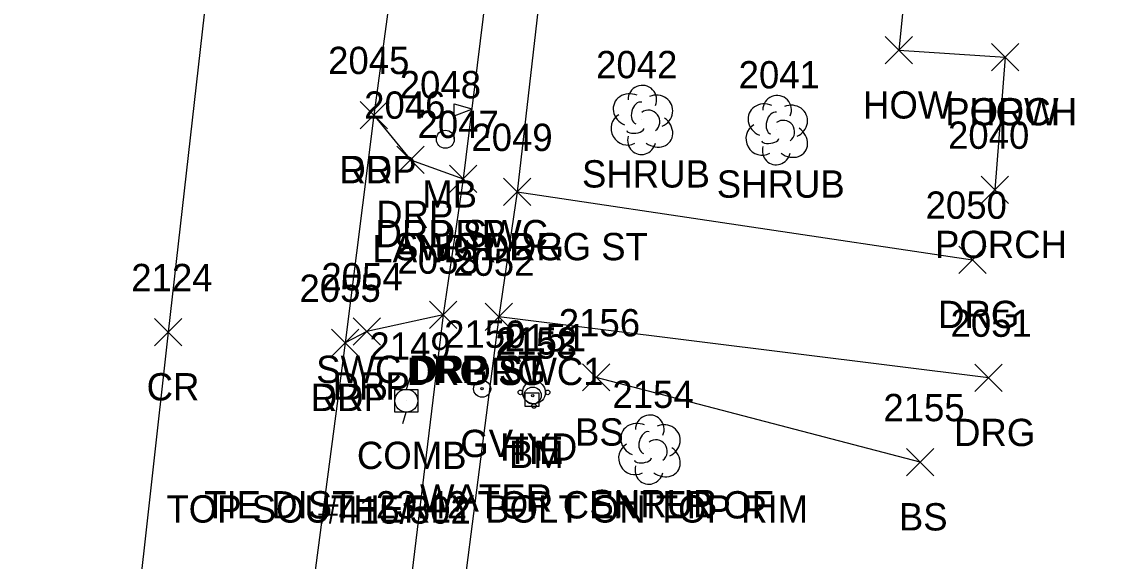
# Model space of a CAD drawing. Extents: x 1651305 to 1654558, y 539481 to 548441.
# Drawn here: x 1654363.2 to 1654443.3, y 544258.1 to 544297.6 of the extents above; entities that cross this region are included whole.
import ezdxf

# ---------------------------------------------------------------- set-up
doc = ezdxf.new("R2010")
doc.units = 0
for name, color, linetype in [('C_A', 7, 'Continuous'), ('C_C', 7, 'Continuous'), ('C_I', 7, 'Continuous'), ('CBP', 7, 'Continuous'), ('CPBM', 7, 'Continuous'), ('L_A', 7, 'Continuous'), ('L_C', 7, 'Continuous'), ('L_I', 7, 'Continuous'), ('L_TIC', 7, 'Continuous'), ('LBC', 7, 'Continuous'), ('LBF', 7, 'Continuous'), ('LELB', 7, 'Continuous'), ('LMB', 7, 'Continuous'), ('LSH', 7, 'Continuous'), ('P_A', 7, 'Continuous'), ('P_I', 7, 'Continuous'), ('P_TIC', 7, 'Continuous'), ('PET', 7, 'Continuous'), ('PRC', 7, 'Continuous'), ('R_A', 7, 'Continuous'), ('R_I', 7, 'Continuous'), ('R_TIC', 7, 'Continuous'), ('RDG', 7, 'Continuous'), ('RDP', 7, 'Continuous'), ('RSW', 7, 'Continuous'), ('U_A', 7, 'Continuous'), ('U_C', 7, 'Continuous'), ('U_I', 7, 'Continuous'), ('UP', 7, 'Continuous'), ('UWFH', 7, 'Continuous'), ('UWV', 7, 'Continuous')]:
    doc.layers.add(name, color=color, linetype=linetype)

msp = doc.modelspace()

# ---------------------------------------------------------------- linework, layer by layer
at = {"layer": 'CBP'}
for radius in [0.625, 0.0833]:
    msp.add_circle((1654400.576, 544270.202), radius, dxfattribs=at)
at = {"layer": 'CPBM'}
for p, q in [((1654400.022, 544269.4), (1654400.022, 544270.4)), ((1654400.022, 544270.4), (1654401.022, 544270.4)), ((1654400.525, 544269.9), (1654400.525, 544269.9)), ((1654400.525, 544269.9), (1654400.525, 544269.9)), ((1654401.022, 544270.4), (1654401.022, 544269.4)), ((1654401.022, 544269.4), (1654400.022, 544269.4))]:
    msp.add_line(p, q, dxfattribs=at)
at = {"layer": 'L_TIC'}
for points in [[(1654426.363, 544294.483), (1654428.363, 544296.483)], [(1654428.363, 544294.483), (1654426.363, 544296.483)], [(1654434.139, 544293.979), (1654436.139, 544295.979)], [(1654436.139, 544293.979), (1654434.139, 544295.979)], [(1654434.139, 544293.979), (1654436.139, 544295.979)], [(1654436.139, 544293.979), (1654434.139, 544295.979)], [(1654433.393, 544284.264), (1654435.393, 544286.264)], [(1654435.393, 544284.264), (1654433.393, 544286.264)], [(1654404.231, 544270.535), (1654406.231, 544272.535)], [(1654406.231, 544270.535), (1654404.231, 544272.535)], [(1654427.928, 544264.323), (1654429.928, 544266.323)], [(1654429.928, 544264.323), (1654427.928, 544266.323)]]:
    msp.add_lwpolyline(points, dxfattribs=at)
at = {"layer": 'LBC'}
msp.add_lwpolyline([(1654438.268, 544331.324), (1654431.161, 544332.043), (1654429.48, 544317.688), (1654428.83, 544310.138), (1654427.363, 544295.483), (1654435.139, 544294.979)], dxfattribs=at)
at = {"layer": 'LBF'}
msp.add_lwpolyline([(1654435.139, 544294.979), (1654434.393, 544285.264)], dxfattribs=at)
at = {"layer": 'LELB'}
msp.add_lwpolyline([(1654428.928, 544265.323), (1654405.231, 544271.535)], dxfattribs=at)
at = {"layer": 'LMB'}
for p, q in [((1654394.831, 544291.567), (1654396.125, 544291.185)), ((1654394.837, 544288.975), (1654394.836, 544291.57)), ((1654394.836, 544290.668), (1654396.118, 544291.176)), ((1654394.181, 544288.967), (1654394.181, 544288.967))]:
    msp.add_line(p, q, dxfattribs=at)
msp.add_circle((1654394.181, 544288.966), 0.656, dxfattribs=at)
at = {"layer": 'LSH'}
for p, q in [((1654408.551, 544290.431), (1654408.551, 544290.431)), ((1654408.551, 544290.431), (1654408.551, 544290.431)), ((1654418.416, 544289.685), (1654418.416, 544289.685)), ((1654418.416, 544289.685), (1654418.416, 544289.685)), ((1654409.099, 544266.297), (1654409.099, 544266.297)), ((1654409.099, 544266.297), (1654409.099, 544266.297))]:
    msp.add_line(p, q, dxfattribs=at)
for centre in [(1654408.598, 544291.865), (1654418.463, 544291.119), (1654409.146, 544267.731)]:
    msp.add_arc(centre, 1.047, 335.52715, 180.95627, dxfattribs=at)
for centre, major_axis, ratio, start_param, end_param in [((1654407.759, 544291.097), (1.21, -0.512), 0.895232, 1.570796, 4.712389), ((1654409.592, 544291.014), (-1.141, -0.483), 0.949671, 1.570796, 4.712389), ((1654408.342, 544290.889), (-0.208, -0.792), 0.645439, 3.141593, 6.283185), ((1654417.624, 544290.352), (1.21, -0.512), 0.895232, 1.570796, 4.712389), ((1654419.458, 544290.269), (-1.141, -0.483), 0.949671, 1.570796, 4.712389), ((1654407.468, 544289.722), (0.584, -1.042), 0.959034, 3.141593, 6.283185), ((1654409.051, 544290.264), (-0.5, 0.667), 0.989748, 3.141593, 6.283185), ((1654409.551, 544289.598), (-1.09, 0.792), 0.841452, 1.570796, 4.712389), ((1654418.208, 544290.144), (-0.208, -0.792), 0.645439, 3.141593, 6.283185), ((1654408.093, 544289.681), (-0.625, -0.083), 0.423636, 0, 3.141593), ((1654417.333, 544288.977), (0.584, -1.042), 0.959034, 3.141593, 6.283185), ((1654418.916, 544289.519), (-0.5, 0.667), 0.989748, 3.141593, 6.283185), ((1654419.416, 544288.852), (-1.09, 0.792), 0.841452, 1.570796, 4.712389), ((1654408.551, 544288.931), (0.265, 1.061), 0.942809, 1.570796, 4.712389), ((1654417.958, 544288.935), (-0.625, -0.083), 0.423636, 0, 3.141593), ((1654418.416, 544288.185), (0.265, 1.061), 0.942809, 1.570796, 4.712389), ((1654408.307, 544266.963), (1.21, -0.512), 0.895232, 1.570796, 4.712389), ((1654410.141, 544266.88), (-1.141, -0.483), 0.949671, 1.570796, 4.712389), ((1654408.891, 544266.755), (-0.208, -0.792), 0.645439, 3.141593, 6.283185), ((1654408.016, 544265.588), (0.584, -1.042), 0.959034, 3.141593, 6.283185), ((1654409.599, 544266.13), (-0.5, 0.667), 0.989748, 3.141593, 6.283185), ((1654410.099, 544265.464), (-1.09, 0.792), 0.841452, 1.570796, 4.712389), ((1654409.099, 544264.797), (0.265, 1.061), 0.942809, 1.570796, 4.712389), ((1654408.641, 544265.547), (-0.625, -0.083), 0.423636, 0, 3.141593)]:
    msp.add_ellipse(centre, major_axis=major_axis, ratio=ratio, start_param=start_param, end_param=end_param, dxfattribs=at)
at = {"layer": 'P_TIC'}
for points in [[(1654387.941, 544289.736), (1654389.941, 544291.736)], [(1654389.941, 544289.736), (1654387.941, 544291.736)], [(1654372.889, 544273.842), (1654374.889, 544275.842)], [(1654374.889, 544273.842), (1654372.889, 544275.842)], [(1654385.845, 544273.06), (1654387.845, 544275.06)], [(1654387.845, 544273.06), (1654385.845, 544275.06)]]:
    msp.add_lwpolyline(points, dxfattribs=at)
at = {"layer": 'PET'}
msp.add_lwpolyline([(1654345.042, 544588.36), (1654350.59, 544607.191), (1654356.582, 544624.309), (1654366.692, 544597.705), (1654378.699, 544565.627), (1654388.798, 544536.019), (1654394.392, 544506.433), (1654399.121, 544481.008), (1654401.125, 544462.893), (1654401.531, 544436.346), (1654401.825, 544421.309), (1654397.366, 544359.696), (1654394.392, 544336.586), (1654391.404, 544308.963), (1654388.941, 544290.736), (1654386.845, 544274.06), (1654380.974, 544229.445), (1654377.749, 544202.908), (1654375.628, 544181.037), (1654372.192, 544149.754), (1654366.612, 544105.723), (1654362.798, 544072.788)], dxfattribs=at)
at = {"layer": 'PRC'}
msp.add_lwpolyline([(1654350.59, 544607.191), (1654355.931, 544592.699), (1654363.685, 544570.628), (1654372.223, 544542.272), (1654380.244, 544505.389), (1654384.95, 544473.916), (1654386.821, 544433.75), (1654385.713, 544395.522), (1654383.86, 544365.997), (1654380.919, 544339.646), (1654377.996, 544311.086), (1654373.889, 544274.842), (1654369.008, 544231.012), (1654366.63, 544212.463), (1654362.444, 544177.974), (1654359.488, 544151.886), (1654354.071, 544107.932), (1654348.42, 544063.008)], dxfattribs=at)
at = {"layer": 'R_TIC'}
for points in [[(1654387.941, 544289.736), (1654389.941, 544291.736)], [(1654389.941, 544289.736), (1654387.941, 544291.736)], [(1654390.633, 544286.466), (1654392.633, 544288.466)], [(1654392.633, 544286.466), (1654390.633, 544288.466)], [(1654394.487, 544285.058), (1654396.487, 544287.058)], [(1654396.487, 544285.058), (1654394.487, 544287.058)], [(1654394.487, 544285.058), (1654396.487, 544287.058)], [(1654396.487, 544285.058), (1654394.487, 544287.058)], [(1654398.432, 544284.106), (1654400.432, 544286.106)], [(1654400.432, 544284.106), (1654398.432, 544286.106)], [(1654398.432, 544284.106), (1654400.432, 544286.106)], [(1654400.432, 544284.106), (1654398.432, 544286.106)], [(1654431.752, 544279.142), (1654433.752, 544281.142)], [(1654433.752, 544279.142), (1654431.752, 544281.142)], [(1654393.013, 544275.122), (1654395.013, 544277.122)], [(1654395.013, 544275.122), (1654393.013, 544277.122)], [(1654393.013, 544275.122), (1654395.013, 544277.122)], [(1654395.013, 544275.122), (1654393.013, 544277.122)], [(1654397.089, 544274.966), (1654399.089, 544276.966)], [(1654399.089, 544274.966), (1654397.089, 544276.966)], [(1654397.089, 544274.966), (1654399.089, 544276.966)], [(1654399.089, 544274.966), (1654397.089, 544276.966)], [(1654387.448, 544273.9), (1654389.448, 544275.9)], [(1654389.448, 544273.9), (1654387.448, 544275.9)], [(1654385.845, 544273.06), (1654387.845, 544275.06)], [(1654387.845, 544273.06), (1654385.845, 544275.06)], [(1654432.922, 544270.501), (1654434.922, 544272.501)], [(1654434.922, 544270.501), (1654432.922, 544272.501)]]:
    msp.add_lwpolyline(points, dxfattribs=at)
at = {"layer": 'RDG'}
for points in [[(1654399.432, 544285.106), (1654432.752, 544280.142)], [(1654433.922, 544271.501), (1654398.089, 544275.966)]]:
    msp.add_lwpolyline(points, dxfattribs=at)
at = {"layer": 'RDP'}
for points in [[(1654388.941, 544290.736), (1654391.633, 544287.466), (1654395.487, 544286.058)], [(1654394.013, 544276.122), (1654388.448, 544274.9), (1654386.845, 544274.06)]]:
    msp.add_lwpolyline(points, dxfattribs=at)
at = {"layer": 'RSW'}
for points in [[(1654407.404, 544661.775), (1654407.293, 544658.868), (1654407.962, 544657.877), (1654443.269, 544654.592), (1654438.81, 544619.894), (1654433.558, 544580.17), (1654430.136, 544553.995), (1654428.025, 544537.281), (1654424.833, 544512.838), (1654419.77, 544473.615), (1654412.659, 544419.662), (1654404.122, 544354.774), (1654402.102, 544339.773), (1654395.487, 544286.058), (1654394.013, 544276.122), (1654388.386, 544229.583), (1654383.891, 544196.376), (1654382.201, 544184.333), (1654378.352, 544149.148), (1654372.361, 544105.495), (1654368.546, 544072.052)], [(1654433.769, 544447.317), (1654420.392, 544448.732), (1654416.298, 544419.47), (1654415.224, 544408.685), (1654412.657, 544388.617), (1654423.018, 544387.519), (1654429.579, 544386.827), (1654429.097, 544382.97), (1654422.687, 544383.714), (1654411.983, 544384.286), (1654408, 544354.107), (1654405.993, 544338.287), (1654403.211, 544318.213), (1654402.851, 544314.962), (1654399.432, 544285.106), (1654398.089, 544275.966), (1654392.335, 544231.256), (1654397.808, 544230.762), (1654412.219, 544229.296)]]:
    msp.add_lwpolyline(points, dxfattribs=at)
at = {"layer": 'UP'}
for p, q in [((1654391.575, 544271.489), (1654391.325, 544270.656)), ((1654390.491, 544268.989), (1654390.491, 544270.656)), ((1654390.491, 544270.656), (1654392.158, 544270.656)), ((1654392.158, 544270.656), (1654392.158, 544268.989)), ((1654391.325, 544269.822), (1654391.325, 544269.822)), ((1654392.158, 544268.989), (1654390.491, 544268.989)), ((1654391.075, 544268.156), (1654391.325, 544268.989))]:
    msp.add_line(p, q, dxfattribs=at)
msp.add_circle((1654391.325, 544269.822), 0.833, dxfattribs=at)
at = {"layer": 'UWFH'}
msp.add_line((1654400.672, 544270.433), (1654400.672, 544270.433), dxfattribs=at)
for centre, radius in [((1654400.672, 544270.433), 0.833), ((1654399.672, 544270.433), 0.167), ((1654401.672, 544270.433), 0.167), ((1654400.672, 544269.433), 0.167)]:
    msp.add_circle(centre, radius, dxfattribs=at)
at = {"layer": 'UWV'}
for radius in [0.625, 0.0833]:
    msp.add_circle((1654396.874, 544270.696), radius, dxfattribs=at)

# ---------------------------------------------------------------- texts
at = {"layer": 'C_A'}
for s, p in [('TIE', (1654398.655, 544265.202)), ('BM', (1654398.84, 544264.9))]:
    msp.add_text(s, height=2, dxfattribs=at).set_placement(p)
at = {"layer": 'C_C'}
for s, p in [('TOP SOUTHERLY BOLT ON TOP RIM', (1654373.769, 544260.9)), ('TIE DIST=23.42 TOP CENTER OF', (1654376.537, 544261.202))]:
    msp.add_text(s, height=2, dxfattribs=at).set_placement(p)
at = {"layer": 'C_I'}
for s, p in [('2153', (1654397.832, 544272.9)), ('2152', (1654397.883, 544273.202))]:
    msp.add_text(s, height=2, dxfattribs=at).set_placement(p)
at = {"layer": 'L_A'}
for s, p in [('HOW', (1654424.749, 544290.483)), ('PORCH', (1654430.761, 544289.979)), ('HOW', (1654432.525, 544289.979)), ('SHRUB', (1654404.181, 544285.431)), ('SHRUB', (1654414.046, 544284.685)), ('MB', (1654392.488, 544283.966)), ('PORCH', (1654430.015, 544280.264)), ('BS', (1654403.672, 544266.535)), ('SHRUB', (1654404.729, 544261.297)), ('BS', (1654427.369, 544260.323))]:
    msp.add_text(s, height=2, dxfattribs=at).set_placement(p)
at = {"layer": 'L_C'}
msp.add_text('LANDRY', height=2, dxfattribs=at).set_placement((1654388.842, 544279.966))
at = {"layer": 'L_I'}
for s, p in [('2042', (1654405.212, 544293.431)), ('2041', (1654415.645, 544292.685)), ('2048', (1654390.842, 544291.966)), ('2040', (1654430.968, 544288.264)), ('2156', (1654402.483, 544274.535)), ('2154', (1654406.407, 544269.297)), ('2155', (1654426.235, 544268.323))]:
    msp.add_text(s, height=2, dxfattribs=at).set_placement(p)
at = {"layer": 'P_A'}
for s, p in [('RDP', (1654386.429, 544285.736)), ('CR', (1654372.322, 544269.842)), ('RDP', (1654384.333, 544269.06))]:
    msp.add_text(s, height=2, dxfattribs=at).set_placement(p)
at = {"layer": 'P_I'}
for s, p in [('2045', (1654385.603, 544293.736)), ('2124', (1654371.197, 544277.842)), ('2055', (1654383.506, 544277.06))]:
    msp.add_text(s, height=2, dxfattribs=at).set_placement(p)
at = {"layer": 'R_A'}
for s, p in [('DRP', (1654386.429, 544285.736)), ('DRP', (1654389.121, 544282.466)), ('DRP SWC', (1654389.069, 544281.058)), ('DRP', (1654392.975, 544281.058)), ('SWC1 DRG ST', (1654390.432, 544280.106)), ('DRG', (1654396.92, 544280.106)), ('DRG', (1654430.24, 544275.142)), ('SWC DRP ST', (1654384.73, 544271.122)), ('DRG SWC1', (1654391.349, 544270.966)), ('DRP', (1654391.501, 544271.122)), ('DRG', (1654395.577, 544270.966)), ('DRP', (1654385.937, 544269.9)), ('DRP', (1654384.333, 544269.06)), ('DRG', (1654431.41, 544266.501))]:
    msp.add_text(s, height=2, dxfattribs=at).set_placement(p)
at = {"layer": 'R_I'}
for s, p in [('2045', (1654385.603, 544293.736)), ('2046', (1654388.24, 544290.466)), ('2047', (1654392.148, 544289.058)), ('2047', (1654392.148, 544289.058)), ('2049', (1654396.086, 544288.106)), ('2049', (1654396.086, 544288.106)), ('2050', (1654429.327, 544283.142)), ('2053', (1654390.675, 544279.122)), ('2053', (1654390.675, 544279.122)), ('2052', (1654394.75, 544278.966)), ('2052', (1654394.75, 544278.966)), ('2054', (1654385.11, 544277.9)), ('2055', (1654383.506, 544277.06)), ('2051', (1654431.15, 544274.501))]:
    msp.add_text(s, height=2, dxfattribs=at).set_placement(p)
at = {"layer": 'U_A'}
for s, p in [('GV', (1654395.275, 544265.696)), ('HYD', (1654398.191, 544265.433)), ('COMB', (1654387.71, 544264.822))]:
    msp.add_text(s, height=2, dxfattribs=at).set_placement(p)
at = {"layer": 'U_C'}
for s, p in [('WATER', (1654392.331, 544261.696)), ('#415/502', (1654384.884, 544260.822))]:
    msp.add_text(s, height=2, dxfattribs=at).set_placement(p)
at = {"layer": 'U_I'}
for s, p in [('2150', (1654394.094, 544273.696)), ('2151', (1654398.546, 544273.433)), ('2149', (1654388.624, 544272.822))]:
    msp.add_text(s, height=2, dxfattribs=at).set_placement(p)

doc.saveas('drawing.dxf')
